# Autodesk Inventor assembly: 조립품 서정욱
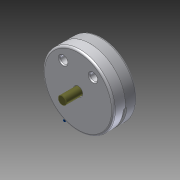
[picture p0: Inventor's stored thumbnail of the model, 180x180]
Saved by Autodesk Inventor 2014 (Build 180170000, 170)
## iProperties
Created: 2015-05
Part Number: 조립품 서정욱
Document SubType Name: Assembly
Designer: USER
Author: USER
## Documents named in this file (10)
- C:\Users\basic\Desktop\Inventor2급-서정욱\조립품 서정욱.iam
- C:\Users\basic\Desktop\Inventor2급-서정욱\서정욱.ipt
- C:\Users\basic\Desktop\Inventor2급-서정욱\20150513-2급공용부품\M 10 x 35.ipt
- C:\Users\basic\Desktop\Inventor2급-서정욱\20150513-2급공용부품\덮개.ipt
- C:\Users\basic\Desktop\Inventor2급-서정욱\20150513-2급공용부품\멈춤링.ipt
- C:\Users\basic\Desktop\Inventor2급-서정욱\20150513-2급공용부품\베어링62_22.ipt
- C:\Users\basic\Desktop\Inventor2급-서정욱\20150513-2급공용부품\슬라이더.ipt
- C:\Users\basic\Desktop\Inventor2급-서정욱\20150513-2급공용부품\슬라이더2.ipt
- C:\Users\basic\Desktop\Inventor2급-서정욱\20150513-2급공용부품\축.ipt
- C:\Users\basic\Desktop\Inventor2급-서정욱\20150513-2급공용부품\평행핀.ipt
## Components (2 placed, 1 different names)
1. M 10 x 35:1
2. M 10 x 35:2
